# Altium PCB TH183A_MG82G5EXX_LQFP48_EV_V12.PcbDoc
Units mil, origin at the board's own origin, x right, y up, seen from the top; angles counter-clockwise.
Board outline 3155 x 2110 mil, 2 copper layers (Top Layer, Bottom Layer); 49 components, 63 nets, 295 pads, 183 vias.
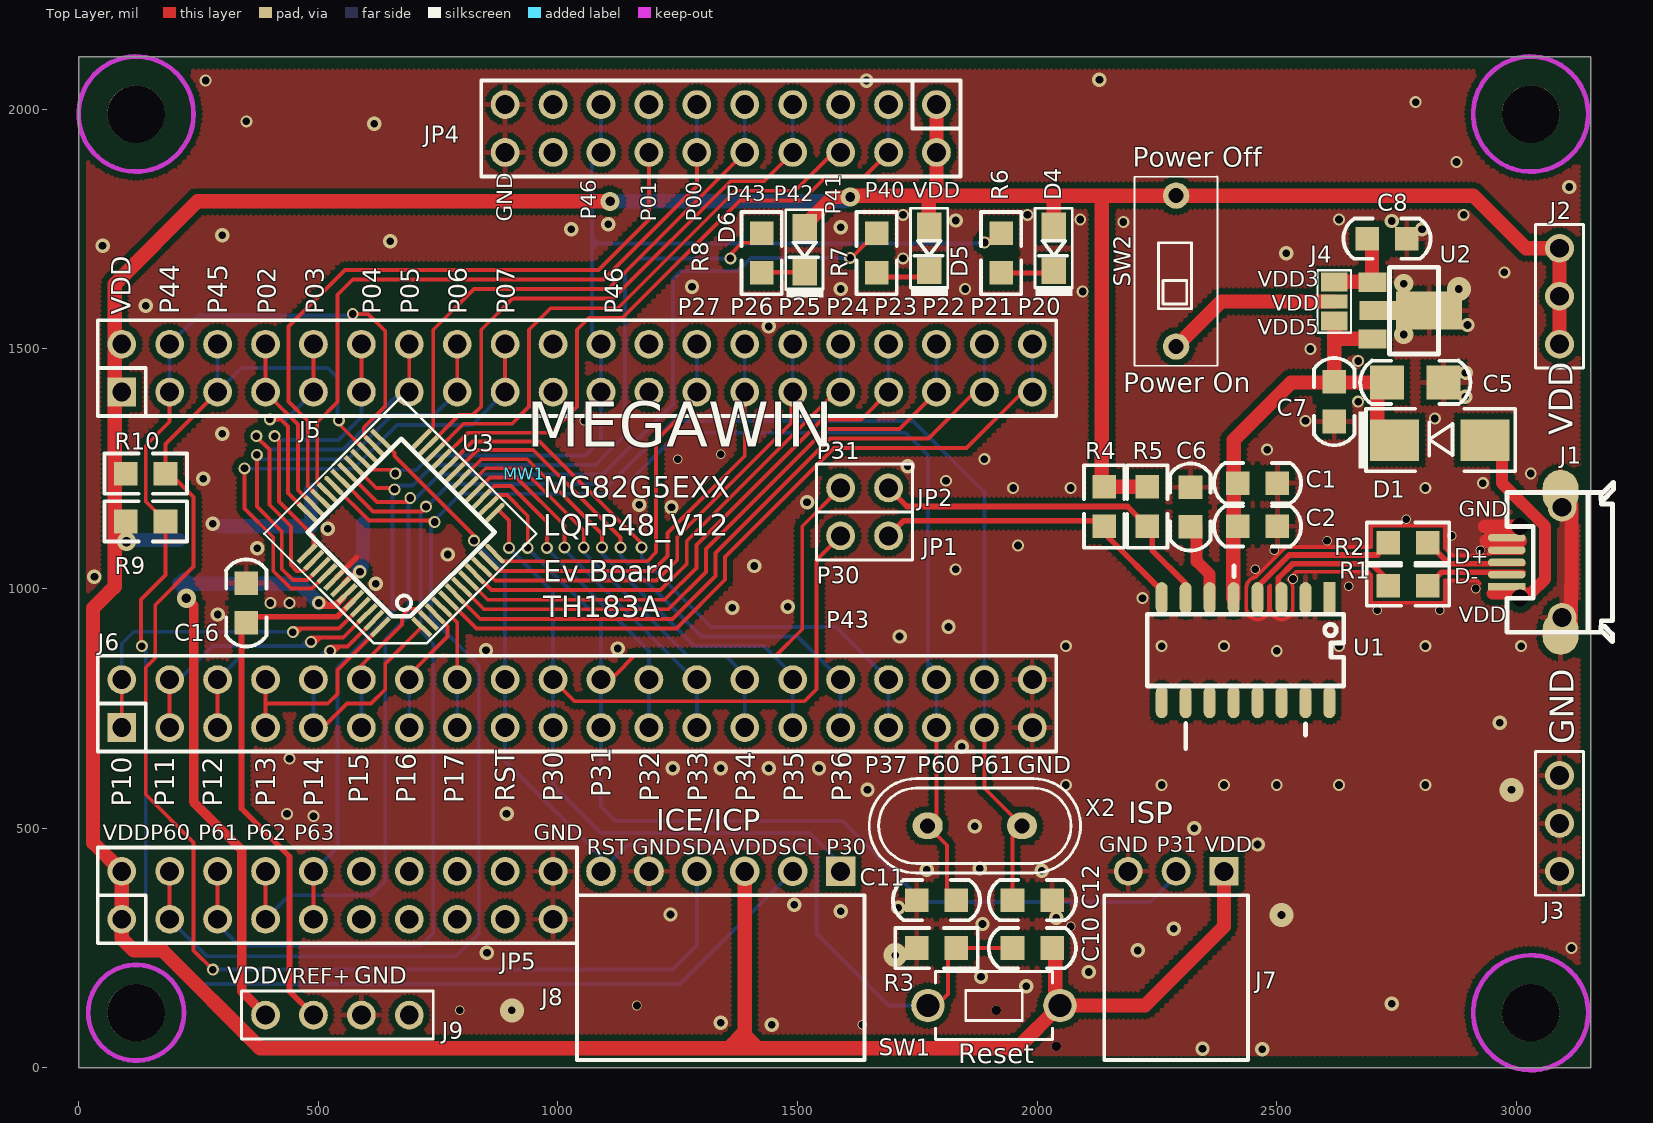
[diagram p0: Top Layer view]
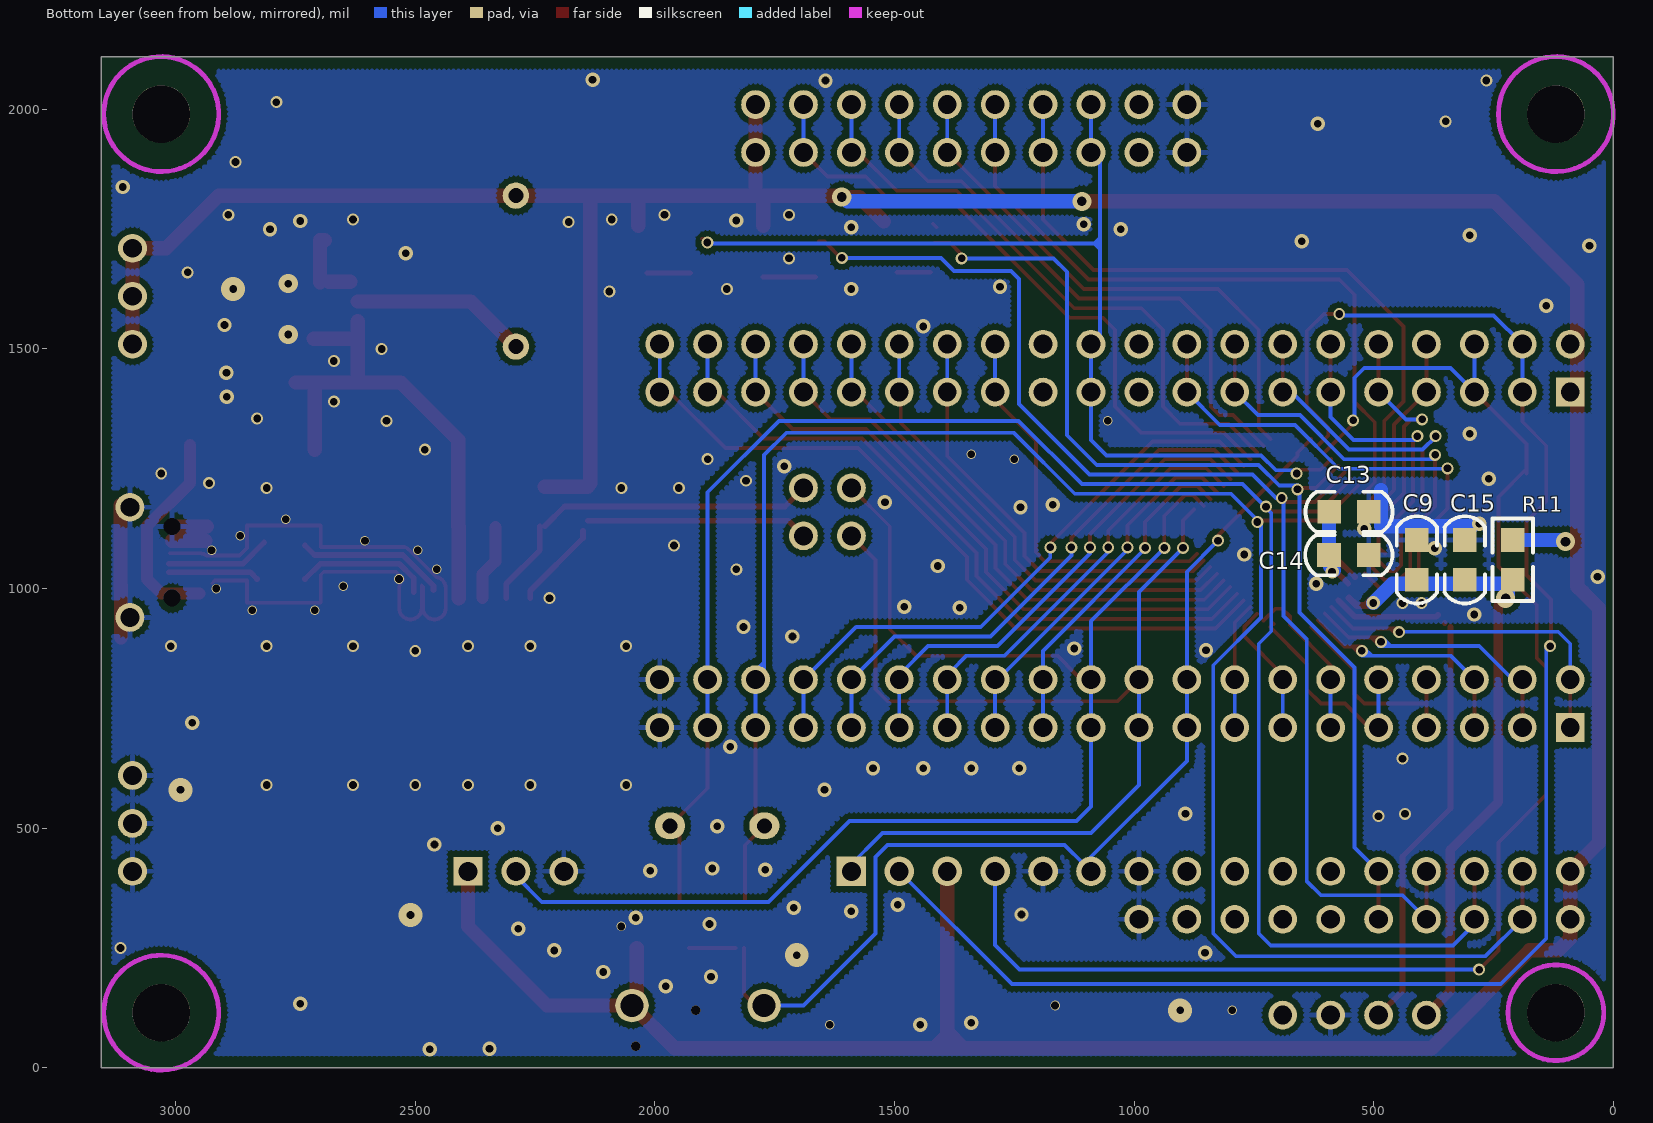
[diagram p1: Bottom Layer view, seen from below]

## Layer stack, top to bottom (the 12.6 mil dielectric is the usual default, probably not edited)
Top Layer: signal copper 1.4
Dielectric: dielectric 12.6, FR-4, Dk 4.8
Bottom Layer: signal copper 1.4

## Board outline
0,0 0,2110 3155,2110 3155,0

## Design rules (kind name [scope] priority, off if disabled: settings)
Clearance 12 [All] p1 off: gap=12
Clearance 7 [All] p2 off: gap=7
Clearance 6 [All] p3: gap=6
ComponentClearance [All] p1 off: gap=10 collisioncheckmode=3 verticalgap=10 showdistances=FALSE
HoleSize [All] p1: absolutevalues=TRUE maxlimit=500 minlimit=1 maxpercent=80.000 minpercent=20.000
MinimumSolderMaskSliver [All] p1 off: minsoldermaskwidth=10
PolygonConnect VIA [ISVIA] p1: connectstyle=Direct reliefconductorwidth=10 reliefentries=4 polygonreliefangle="90 Angle"
PolygonConnect [All] p2: connectstyle=Relief reliefconductorwidth=10 reliefentries=4 polygonreliefangle="90 Angle"
RoutingVias [All] p1: holewidth=16 width=25 viastyle="Through Hole" minholewidth=16 minwidth=24 maxholewidth=28 maxwidth=50
SilkToSilkClearance [All] p1 off: silktosilkclearance=10
SilkscreenOverComponentPads [All] p1 off: minsilkscreentomaskgap=10
SolderMaskExpansion [All] p1 off: expansion=4
Width [All] p1: maxlimit=200 minlimit=6 preferedwidth=10
23 further rules are at their usual default settings.

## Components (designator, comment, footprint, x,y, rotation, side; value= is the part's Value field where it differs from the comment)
C1 "4.7uF" 0805C 2460,1220 r0 top
C2 "0.1uF" 0805C 2460,1130 r0 top
C5 "4.7uF" 1206C 2789.06,1430 r0 top
C6 "1uF" 0805C 2320,1170 r90 top
C7 "0.1uF" 0805C 2620,1390 r270 top
C8 "4.7uF" 0805C 2730,1730 r0 top
C9 "0.1uF" 0805C 410,1060 r90 bottom
C10 "1u" 0805C 1990,250 r180 top
C11 "NC" 0805C 1790,350 r180 top
C12 "NC" 0805C 1990,350 r0 top
C13 "4.7uF" 0805C 551.61,1160 r180 bottom
C14 "0.1uF" 0805C 552,1070 r0 bottom
C15 "4.7uF" 0805C 310,1060 r90 bottom
C16 "0.1uF" 0805C 350,970 r90 top
D1 "1N5817" D5817_SMD_1 2840,1310 r0 top
D4 "Green" 0805D 2035,1710 r270 top
D5 "Red" 0805D 1775,1710 r270 top
D6 "Green" 0805D 1515,1706.92 r270 top
J1 "Micro USB母座" JACK_USB_SMD290X220P065 2980,1054.72 r180 top
J2 "*" PS3P254 3090,1510 r90 top
J3 "*" PS3P254 3090,610 r270 top
J4 "*" JUMP3_SMD 2620,1599 r90 top
J5 "CON40A" PS20X2P254 90,1410 r0 top locked
J6 "CON40A" PS20X2P254 90,710 r0 top locked
J7 "*" PS3P254f_90 2390,410 r180 top
J8 "*" PS6P254F_90 1590,410 r180 top locked
J9 "CON4" PS4P254 390,110 r0 top
JP1 "JUMPER2" PS2P254 1590,1110 r0 top
JP2 "JUMPER2" PS2P254 1590,1210 r0 top
JP4 "*" PS10X2P254 1790,2010 r180 top
JP5 "*" PS10X2P254 90,310 r0 top
MW1 "MW-A4" MEGAWIN_T 930,1240 r0 top
R1 "22" 0805R 2774,1006 r180 top
R2 "22" 0805R 2774,1096 r180 top
R3 "47K" 0805R 1790,250 r0 top
R4 "4.7K" 0805R 2140,1171.34 r270 top
R5 "4.7K" 0805R 2230,1171.34 r270 top
R6 "1K" 0805R 1925,1700 r270 top
R7 "1K" 0805R 1665,1700 r270 top
R8 "1K" 0805R 1425,1700 r270 top
R9 "4.7K" 0805R 140,1140 r180 top
R10 "4.7K" 0805R 140,1240 r180 top
R11 "10" 0805R 210,1060 r270 bottom
SW1 "SW TACT-SPST" SW_T_2P 1910,130 r180 top locked
SW2 "-" DIP2_SW 2290,1505.04 r90 top
U1 "MA111AS16" SO16_150P127 2435,871.5 r270 top
U2 "AIC1734-33(SOT-89)" SOT89 2700,1580 r270 top
U3 "MG82FG5EXX" LQFP48_7X7_050 672.94,1115.7 r45 top (schematic designator U1)
X2 "NC" X49U 1870,505 r180 top

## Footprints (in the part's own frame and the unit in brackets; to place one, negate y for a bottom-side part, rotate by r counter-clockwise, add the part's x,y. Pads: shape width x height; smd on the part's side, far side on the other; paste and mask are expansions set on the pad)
0805C [mm]
  rect 1.25x1.25 smd: 1(-1.05,0) 2(1.05,0)
  silkscreen extent -2.31,-1.07 2.31,1.07
0805D [mm]
  rect 1.4x1.3 smd: 1(-1.192,0) 2(1.192,0)
  silkscreen extent -2.12,-1 2.54,1
0805R [mm]
  rect 1.25x1.25 smd: 1(-1.05,0) 2(1.05,0)
  silkscreen extent -2.18,-1.07 2.18,1.07
1206C [mm]
  rect 1.8x1.8 smd: 1(-1.5,0) 2(1.5,0)
  silkscreen extent -2.92,-1.15 2.92,1.16
D5817_SMD_1 [mm]
  rect 2.6x2.2 smd: 1(2.39,0) 2(-2.39,0)
  silkscreen extent -4.3,-1.65 4,1.65
DIP2_SW [mm]
  round 1.4 hole 0.8: 1(0,0) 2(8,0)
  silkscreen extent -1.02,-2.2 9.02,2.2
JACK_USB_SMD290X220P065 [mm]
  rect 1.9x1.8 on Mech2: 0(-2.85,-1.15) 0(-2.85,1.15)
  round 0.8 hole 0.9 unplated: 1(-0.7,1.9) 5(-0.7,-1.9)
  rect 2x0.4 smd: 1(0,1.3)
  oval 2x0.4 smd: 2(0,0.65) 3(0,0) 4(0,-0.65) 5(0,-1.3)
  round 1.524 hole 1: 5(-2.931,2.921) 5(-2.931,-2.921)
  oval 1.9x2.3 smd: 5(-2.85,3.75) 5(-2.85,-3.75)
  silkscreen extent -5.65,-4.25 -0.01,4.2
JUMP3_SMD [mil]
  rect 40x55 smd: 1(-41,0) 3(41,0)
  rect 30x55 smd: 2(0,0)
  silkscreen extent -65,-35 65,35
LQFP48_7X7_050 [mm]
  rect 0.254x1.35 smd: 1(-2.75,-4.292) 2(-2.25,-4.292) 3(-1.75,-4.292) 4(-1.25,-4.292) 5(-0.75,-4.292) 6(-0.25,-4.292) 7(0.25,-4.292) 8(0.75,-4.292) 9(1.25,-4.292) 10(1.75,-4.292) 11(2.25,-4.292) 25(2.763,4.292) 26(2.263,4.292) 27(1.763,4.292) 28(1.263,4.292) 29(0.763,4.292) 30(0.263,4.292) 31(-0.237,4.292) 33(-1.237,4.292) 34(-1.737,4.292) 35(-2.237,4.292) 36(-2.737,4.292)
  oval 0.254x1.35 smd: 12(2.75,-4.292) 32(-0.737,4.292)
  oval 1.35x0.254 smd: 13(4.286,-2.744)
  rect 1.35x0.254 smd: 14(4.286,-2.244) 15(4.286,-1.744) 16(4.286,-1.244) 17(4.286,-0.744) 18(4.286,-0.244) 19(4.286,0.256) 20(4.286,0.756) 21(4.286,1.256) 22(4.286,1.756) 23(4.286,2.256) 24(4.286,2.756) 37(-4.286,2.756) 38(-4.286,2.256) 39(-4.286,1.756) 40(-4.286,1.256) 41(-4.286,0.756) 42(-4.286,0.256) 43(-4.286,-0.244) 44(-4.286,-0.744) 45(-4.286,-1.244) 46(-4.286,-1.744) 47(-4.286,-2.244) 48(-4.286,-2.744)
  silkscreen extent -5.15,-5.09 5.05,5.11
MEGAWIN_T [mil]
PS2P254 [mil]
  round 60 hole 39.37: 1(0,0) 2(100,0)
  silkscreen extent -50,-50 150,50
PS3P254 [mil]
  round 60 hole 39.37: 1(0,0) 2(100,0) 3(200,0)
  silkscreen extent -50,-50 250,50
PS3P254f_90 [mil]
  rect 60x60 hole 39.37: 1(0,0)
  round 60 hole 39.37: 2(100,0) 3(200,0)
  silkscreen extent -50,50 250,394
PS4P254 [mil]
  round 60 hole 39.37: 1(0,0) 2(100,0) 3(200,0) 4(300,0)
  silkscreen extent -50,-50 350,50
PS6P254F_90 [mil]
  rect 62x62 hole 39.37: 1(0,0)
  round 62 hole 39.37: 2(100,0) 3(200,0) 4(300,0) 5(400,0) 6(500,0)
  silkscreen extent -50,50 550,394
PS10X2P254 [mil]
  round 60 hole 39.37: 1(0,0) 2(0,100) 3(100,0) 4(100,100) 5(200,0) 6(200,100) 7(300,0) 8(300,100) 9(400,0) 10(400,100) 11(500,0) 12(500,100) 13(600,0) 14(600,100) 15(700,0) 16(700,100) 17(800,0) 18(800,100) 19(900,0) 20(900,100)
  silkscreen extent -50,-50 950,150
PS20X2P254 [mil]
  rect 60x60 hole 39.37: 1(0,0)
  round 60 hole 39.37: 2(0,100) 3(100,0) 4(100,100) 5(200,0) 6(200,100) 7(300,0) 8(300,100) 9(400,0) 10(400,100) 11(500,0) 12(500,100) 13(600,0) 14(600,100) 15(700,0) 16(700,100) 17(800,0) 18(800,100) 19(900,0) 20(900,100) 21(1000,0) 22(1000,100) 23(1100,0) 24(1100,100) 25(1200,0) 26(1200,100) 27(1300,0) 28(1300,100) 29(1400,0) 30(1400,100) 31(1500,0) 32(1500,100) 33(1600,0) 34(1600,100) 35(1700,0) 36(1700,100) 37(1800,0) 38(1800,100) 39(1900,0) 40(1900,100)
  silkscreen extent -50,-50 1950,150
SO16_150P127 [mil]
  rect 67x25 smd: 1(-108.5,175)
  oval 67x25 smd: 2(-108.5,125) 3(-108.5,75) 4(-108.5,25) 5(-108.5,-25) 6(-108.5,-75) 7(-108.5,-125) 8(-108.5,-175) 9(108.5,-175) 10(108.5,-125) 11(108.5,-75) 12(108.5,-25) 13(108.5,25) 14(108.5,75) 15(108.5,125) 16(108.5,175)
  silkscreen extent -176,-205 206,205
SOT89 [mm]
  rect 1.016x1.5 smd: 1(-1.5,0) 3(1.5,0)
  rect 2x3.5 smd: 2(0,3)
  rect 1.016x2.6 smd: 2(0,0.6)
  silkscreen extent -2.3,0.9 2.3,3.5
SW_T_2P [mil]
  round 70 hole 47.24: 1(-137.79,0) 2(137.79,0)
  silkscreen extent -122,-71 122,71
X49U [mm]
  oval 1.6x1.397 hole 0.8: 1(-2.5,0) 2(2.5,0)
  silkscreen extent -5.6,-2.5 5.6,2.5

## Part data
C1 C5 C8 C13 C15: library part CAP
C2 C6 C7 C9 C14 C16: library part "CAP NP"
C10: library part C
C11 C12: library part "C NP"
D1: library part DIODE_ZD, "Schottky Diode"
D4 D5 D6: library part LED
J1: library part CON5, "Connector"
J2 J3 J4 J7: library part CON3
J8: library part CON6
JP4 JP5: library part CON10X2
R1 R2 R3 R9 R10 R11: library part R
R4 R5 R6 R7 R8: library part R_Dup1
SW2: library part SW-2
U2: library part AIC1734-33(SOT-89)_0
U3: library part MG82FG5C64_LQFP48
X2: library part CRYSTAL

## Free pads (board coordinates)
  round 120 hole 120 unplated: 0(120,115) 0(120,1990) 0(3030,115) 0(3030,1990)

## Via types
v1: diameter 25, hole 16, Top Layer to Bottom Layer, tented both sides, 78 vias
v2: diameter 30, hole 16, Top Layer to Bottom Layer, tented both sides, 72 vias
v3: diameter 20, hole 16, Top Layer to Bottom Layer, tented both sides, 18 vias
v4: diameter 50, hole 16, Top Layer to Bottom Layer, tented both sides, 5 vias
v5: diameter 40, hole 20, Top Layer to Bottom Layer, tented both sides, 4 vias
v6: diameter 20, hole 20, Top Layer to Bottom Layer, tented both sides, 2 vias
v7: diameter 40, hole 16, Top Layer to Bottom Layer, tented both sides, 2 vias
v8: diameter 28, hole 16, Top Layer to Bottom Layer, tented both sides, 2 vias

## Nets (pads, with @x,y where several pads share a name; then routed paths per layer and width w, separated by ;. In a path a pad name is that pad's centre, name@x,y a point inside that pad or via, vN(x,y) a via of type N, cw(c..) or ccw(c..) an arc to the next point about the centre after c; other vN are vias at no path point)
CHIP_VDD: C9.1 C15.1 J9.1 R11.2 U3.43 | length 1345.2
  Top Layer w12: v8@509,976 518,967
  Top Layer w15: v8@510,965 535.8,965 U3.43@551.4,980.6
  Top Layer w20: v5(225,980) 240,965 240,555 340,455 340,160 J9.1
  Bottom Layer w30: R11.2@210,1010 R11.2@220,1010 ; v5@220,980 R11.2@220,1010 ; R11.2@220,1018.66 R11.2@220,1010 ; v8(501,970) 461,1010 R11.2@220,1010
D+: R2.2 U1.4 | length 311.8
  Top Layer w12: U1.4@2462,997 2462,1006 2526,1070 2710,1070 R2.2@2730,1090
D-: R1.2 U1.3 | length 281.1
  Top Layer w12: U1.3@2503.38,993.12 2503.38,1021.92 2533.46,1052 2698,1052 R1.2@2730,1020
GND_POWER: C1.2 C2.2 C5.2 C6.2 C7.2 C8.2 C9.2 C11.2 C12.2 C13.2 C14.1 C15.2 C16.2 J1.4 J1.5 J3.1 J3.2 J3.3 J6.39 J6.40 J7.3 J8.5 J9.3 JP4.19 JP4.20 JP5.19 JP5.20 R3.1 U1.2 U2.2 U3.41 | length 2332.8
  Top Layer w8: 2483.38,1003.34 2486.38,1006.33 2486.38,993.12 ; 2483.5,1001 2483.5,959 cw(c2460,959) 2436.5,959 2436.5,1001 cw(c2460,1001) 2456.14,1024.18 2513.96,1082 cw(c2526,1070) 2526,1087 ; 2486.5,991.07 2486.5,959 ccw(c2510,959) 2533.5,959 2533.5,1001 ccw(c2510,1001) 2524.77,1019.28 2540.5,1035 2690.96,1035 2697.05,1028.9 2697.05,970.39 2850.95,970.39 2850.95,1016.9 ; 2513.98,1082.02 cw(c2526,1070) 2526,1087 ; 2851.04,1017 2917.63,1017 2923.63,1011 ; J1.4@3011.5,1073.6 2948.5,1073.6 ccw(c2948.5,1054.72) 2936.16,1069 2866.38,1069 2850.95,1084.44 2850.95,1131.61 2697.05,1131.61 2697.05,1087 2526,1087
  Top Layer w12: U3.41@539.06,1023.94 580.16,1065.04
  Top Layer w30: 2934.48,1129.53 J1.5@3007.56,1129.53 ; 2938.2,1100 J1.5@3007.56,1100 ; J1.5@3114,898 3114,1005.8 ; 3115,1000 J1.5@3115,1174
  Bottom Layer w30: 295,1130 410,1130 413.39,1130 ; 414.34,1130 485,1130 485,1205.66
  other v1: 3115,250 490,525 435,530 2060,590 2260,590 2390,590 2500,590 2630,590 2810,590 440,645 2500,870 2060,880 2260,880 2390,880 2630,880 2810,880 3010,880 400,970 440,970 2220,980 1830,1040 1960,1090 1950,1210 2070,1210 2810,1210 2930,1220 1810,1225 3030,1240 1890,1270 2480,1290 2560,1350 2830,1355 2670,1390 2670,1475 2570,1500 2095,1620 1850,1625 2975,1660 1720,1689 2180,1765 2090,1770 2630,1770 1720,1780 1980,1780 2890,1780 2875,1890 350,1975 2790,2015 265,2060
  other v2: 2470,39 2345,40 1446,90 1340,94 2740,134 1977,170 1883,190 2108,200 852,240 2210,245 2285,290 1886,300 2040,313 1235,320 1590,327 1710,334 1493,340 2010,411 1770,413 1880,416 2460,466 2328,500 1870,504 893,530 1646,580 1240,625 1340,625 1440,625 1545,625 1843,670 2965,720 850,871 1125.15,874.85 1713,900 1815,920 290,946 1364,960 1480,962 620,1010 33,1025 1410,1047 770,1071 373,1084 520,1125 280,1135 1237,1170 1170,1175 1520,1180 260,1229 1730,1255 300,1323 2893,1400 2894,1450 1440,1547 2898,1550 140,1590 1590,1625 1280,1630 2520,1700 50,1715 650,1725 300,1737 1028,1750 2803,1750 1590,1754 1105,1760 2740,1767 1830,1768 3110,1838 617,1970 1644,2060 2130,2062
  other v3: 1635,90 795,120 1165,130 2070,295 2710,955 2840,955 2915,1000 2650,1005 2533.98,1020 2455,1040 2495,1080 2925,1080 2605,1100 2865,1110 2770,1145 1250,1270 1340,1280 1055,1350
  other v4: 904,120 1704,235 2510,319 2990,580 2880,1625
  other v6: 2040,45 1915,120
  other v7: 2765,1530 2765,1636.37
MA111_RX: JP2.2 R5.2 U1.7 | length 766.3
  Top Layer w12: JP2.2@1700,1220 JP2.2 1728.66,1171.34 2188.66,1171.34 R5.2 ; R5.2@2240,1130 2240,1080 2310,1010 U1.7
MA111_TX: JP1.2 R4.2 U1.8 | length 658.5
  Top Layer w12: JP1.2 1721.34,1141.34 R4.2@2140,1141.34 ; R4.2@2150,1120 2150,1105.34 2260,995.34 U1.8 U1.8@2260,990
NetC6_1: C6.1 U1.6 | length 159.8
  Top Layer w25: C6.1@2333,1128.66 2333,1057 2360,1030 U1.6
NetC13_1: C13.1 C14.2 U3.42 | length 139.7
  Top Layer w12: U3.42@552.98,1010.02 v8@582.97,1040
  Bottom Layer w30: v8@583.5,1038.5 591,1046 C14.2@591,1067 ; C14.2 C13.1@593.34,1135.66
  other v8: 587,1035
NetD1_1: D1.1 J1.1 | length 439.7
  Top Layer w25: 2950,990 3030,990 3060,1020 3060,1130 2970,1220 D1.1@2970,1300
NetD4_2: D4.2 R6.2 | length 91.7
  Top Layer w10: R6.2 D4.2@2016.74,1658.66
NetD5_2: D5.2 R7.2 | length 110
  Top Layer w10: R7.2@1665,1650 D5.2@1775,1650
NetD6_2: D6.2 R8.2 | length 70
  Top Layer w10: R8.2@1425,1660 D6.2@1495,1660
NetJ1_2: J1.2 R1.1 | length 189.8
  Top Layer w12: R1.1@2830,1020 2844,1034 J1.2@3014,1034
NetJ1_3: J1.3 R2.1 | length 216.9
  Top Layer w12: R2.1 2859.34,1052 J1.3@3014,1052
NetJ4_2: J4.2 SW2.1 | length 368.9
  Top Layer w30: SW2.1 2383.96,1599 J4.2
P00: JP4.11 JP4.12 U3.33 | length 1537.6
  Top Layer w8: 498,1307 498,1221.74 ; U3.33 498,1221.74 ; JP4.12 1290,1840 1095,1645 572,1645 540,1613 540,1389 498,1347 498,1221.74
  Bottom Layer w8: JP4.12 JP4.11
P01: JP4.13 JP4.14 U3.34 | length 1472.3
  Top Layer w8: U3.34 478,1213.9 478,1350 438,1390 438,1547 556,1665 1085,1665 1190,1770 JP4.14
  Bottom Layer w8: JP4.14 JP4.13
P02: J5.7 J5.8 U3.35 | length 401.6
  Top Layer w8: J5.8 390,1435 J5.7@416,1409 ; J5.7@400,1405 400,1400 458,1342 458,1206.07 U3.35
  Bottom Layer w8: J5.7@370,1410 J5.7
P03: J5.9 J5.10 U3.36 | length 495.5
  Top Layer w8: v1(399,1353) 422,1353 437,1338 437,1199.23 U3.36 ; J5.9@490,1386 J5.9 J5.10
  Bottom Layer w8: v1(399,1353) 433,1353 J5.9 J5.9@473,1410
P04: J5.11 J5.12 U3.37 | length 636.8
  Top Layer w8: v1(409,1318) 418,1309 418,1182 490,1110 490,1086.23 U3.37 ; J5.11 J5.12
  Bottom Layer w8: v1@409,1310 542,1310 590,1358 J5.11
P05: J5.13 J5.14 U3.38 | length 841.9
  Top Layer w8: v1@370.5,1317.5 398,1290 398,1175 443,1130 443,1049 456,1036 467.61,1036 U3.38 ; J5.13 J5.14
  Bottom Layer w8: v1@370.5,1317.5 398,1290 552,1290 672,1410 J5.13
  other v1: 371,1318
P06: J5.15 J5.16 U3.39 | length 947.1
  Top Layer w8: v1(372,1279) 372,1171 424,1119 424,1041 447,1018 477.45,1018 U3.39 ; J5.15 J5.16
  Bottom Layer w8: v1@372,1270 562,1270 653.87,1361.87 741.87,1361.87 J5.15 J5.15@780,1410
P07: J5.17 J5.18 U3.40 | length 1084.1
  Top Layer w8: v1@346,1250 346,1167 406,1107 406,1037 443,1000 487.29,1000 U3.40 ; J5.17@890,1427.01 J5.18
  Bottom Layer w8: v1@346,1250 573,1250 664.32,1341.32 821.32,1341.32 J5.17 ; J5.17@881.49,1418.51 J5.17@890,1427.01
  other v1: 346,1251
P10: J6.1 J6.2 U3.45 | length 721.6
  Top Layer w8: J6.1 J6.2 ; v1@447,917 465,917 ; v1@450,902 465,917 ; U3.45 543.48,917 465,917
  Bottom Layer w8: J6.2 90,885 115,910 v1@440,910 ; v1@440,909 v1@440,910 ; v1@443,913 v1@440,910
  other v1: 447,909
P11: J6.3 J6.4 U3.46 | length 618.4
  Top Layer w8: J6.3 J6.4@190,790 ; v1@485,898 500,898 ; v1@491,889 500,898 ; v1@492,885 505,898 ; U3.46 552.32,898 505,898 ; 500,898 505,898
  Bottom Layer w8: J6.4@190,790 280,880 465,880 ; v1@479.5,894.5 465,880 ; v1(485,889) 476,880 ; v1@489,880 476,880 ; 465,880 476,880
P12: J6.5 J6.6 U3.47 | length 523.3
  Top Layer w8: J6.5 J6.6 ; v1@525,878.99 545,878.99 ; v1@532,865.99 545,878.99 ; U3.47 561.15,878.99 545,878.99
  Bottom Layer w8: J6.6 340,860 505,860 ; v1@520,875 505,860 ; v1@525,860 515,860 ; v1(525,870) 515,860 ; 505,860 515,860
P13: J6.7 J6.8 U3.48 | length 435.6
  Top Layer w8: J6.7 390,760 ; J6.8 390,760 ; U3.48 540,830 540,780 520,760 390,760
P14: J6.9 J6.10 U3.1 | length 464.4
  Top Layer w8: J6.9 510,710 560,760 610,760 640,790 640,843.77 U3.1 ; J6.10@490,800 500,810 J6.10@515,810 ; U3.1@709.26,926.26 U3.1@710,927
  Bottom Layer w8: J6.9 J6.10@490,800
P15: J6.11 J6.12 U3.2 | length 338.7
  Top Layer w8: J6.12 590,840 675,925 675,942 691,958 705.36,958 U3.2
  Bottom Layer w8: J6.11 J6.12
P16: J6.13 J6.14 U3.3 | length 281.8
  Top Layer w8: J6.14@689.71,810 J6.14 690,820 770,900 770,921.2 U3.3
  Bottom Layer w8: J6.13 J6.14
P17: J6.15 J6.16 U3.4 | length 264.8
  Top Layer w8: U3.4 790,929.04 J6.16
  Bottom Layer w8: J6.15 J6.16
P20: J5.39 J5.40 U3.5 | length 1575
  Top Layer w8: U3.5 830.12,916.76 1247.46,916.76 1349,1018.29 1349,1066.01 1575.99,1293 1853,1293 1970,1410 J5.39
  Bottom Layer w8: J5.39 J5.40
P21: J5.37 J5.38 U3.6 | length 1450.2
  Top Layer w8: U3.6 837.96,936.76 1239.18,936.76 1329,1026.58 1329,1074.29 1567.71,1313 1773,1313 1870,1410 J5.37
  Bottom Layer w8: J5.37 J5.38
P22: J5.35 J5.36 U3.7 | length 1325.5
  Top Layer w8: U3.7 845.8,956.76 1230.89,956.76 1309,1034.86 1309,1082.58 1559.42,1333 1713,1333 J5.35
  Bottom Layer w8: J5.35 J5.36
P23: J5.33 J5.34 U3.8 | length 1200.8
  Top Layer w8: U3.8 853.64,976.76 1222.61,976.76 1289,1043.15 1289,1090.86 1551.14,1353 1633,1353 J5.33
  Bottom Layer w8: J5.33 J5.34
P24: J5.31 J5.32 U3.9 | length 1085.9
  Top Layer w8: U3.9 861.47,996.76 1214.32,996.76 1269,1051.43 1269,1099.15 J5.31@1579.85,1410 ; J5.31@1570,1410 J5.31@1579.85,1410 ; J5.31 J5.31@1579.85,1410
  Bottom Layer w8: J5.31 J5.32
P25: J5.29 J5.30 U3.10 | length 983.3
  Top Layer w8: U3.10 869.31,1016.76 1206.04,1016.76 1249,1059.72 1249,1107.43 1487.05,1345.48 J5.29@1487.05,1405.09 ; J5.29 J5.29@1490,1412.01
  Bottom Layer w8: J5.29 J5.30
P26: J5.27 J5.28 U3.11 | length 904.7
  Top Layer w8: U3.11 877.15,1036.76 1197.76,1036.76 1229,1068 1229,1115.72 1390,1276.72 J5.27
  Bottom Layer w8: J5.27 J5.28
P27: J5.25 J5.26 U3.12 | length 819.9
  Top Layer w8: U3.12 884.75,1057 1187,1057 1205,1076 1205,1309 1290,1394 J5.25
  Bottom Layer w8: J5.25 J5.26
P30/RXD: J6.19 J6.20 J8.1 JP1.1 U3.13 | length 2222.7
  Top Layer w8: U3.13@875,1165 898,1142 v1(898,1085) ; v1@899,1086 v1@900,1085 ; J6.20 1035,765 1515,765 1540,790 1540,1060 JP1.1
  Bottom Layer w8: v1(898,1085) 990,993 J6.20 J6.19 990,590 1090,490 1525,490 J8.1@1597.5,417.5
P31/TXD: J6.21 J6.22 J7.2 JP2.1 U3.14 | length 2876.2
  Top Layer w8: U3.14 877.16,1195 894,1195 937,1152 v1(937,1085) ; J6.22@1100,820 1120,820 ; J6.22@1110,810 1120,820 ; JP2.1 1510,1130 1510,915 1455,860 1160,860 1120,820
  Bottom Layer w8: v1(937,1085) 1090,932 J6.22 J6.21 1090,545 1120,515 1594,515 1763,346 2236,346 J7.2@2290,400
P32: J6.23 J6.24 U3.15 | length 695.7
  Top Layer w8: U3.15 868.13,1213.81 902.19,1213.81 977,1139 v1(977,1085)
  Bottom Layer w8: v1(977,1085) 977,1083 1190,870 J6.24 J6.23
P33: J6.25 J6.26 U3.16 | length 778
  Top Layer w8: U3.16 858.48,1232 914,1232 1014,1132 v1(1014,1086)
  Bottom Layer w8: v1(1014,1086) 1014,1081 1282.5,812.5 1282.5,802.5 1290,795 J6.25
P34: J6.27 J6.28 U3.17 | length 907.1
  Top Layer w8: U3.17 849.64,1251 924,1251 1054,1121 v1(1054,1086)
  Bottom Layer w8: v1(1054,1086) 1054,1076 1270,860 1350,860 1382.5,827.5 1382.5,802.5 1390,795 J6.27
P35: J6.29 J6.30 U3.18 | length 1028.7
  Top Layer w8: U3.18 840.8,1270 936,1270 1092,1114 v1(1092,1086)
  Bottom Layer w8: v1(1092,1086) 1092,1073 1285,880 1430,880 1490,820 J6.30 J6.29
P36: J6.31 J6.32 U3.19 | length 1144.8
  Top Layer w8: U3.19 831.97,1289 948.74,1289 1131,1106.74 v1(1131,1086)
  Bottom Layer w8: v1(1131,1086) 1131,1069 1300,900 1500,900 J6.32 J6.31
P37: J6.33 J6.34 U3.20 | length 1262.7
  Top Layer w8: U3.20 822.13,1307 962,1307 1175,1094 v1(1175,1086)
  Bottom Layer w8: v1(1175,1086) 1175,1065 1320,920 1580,920 J6.34 J6.33
P40: JP4.3 JP4.4 U3.21 | length 1391.5
  Top Layer w8: U3.21 812.29,1325 985,1325 1040,1380 1040,1540 1065,1565 1135,1565 1380,1810 1510,1810 1560,1860 1640,1860 JP4.4
  Bottom Layer w8: JP4.4 JP4.3
P41: JP4.5 JP4.6 U3.22 | length 1299.7
  Top Layer w8: U3.22 803.45,1344 904,1344 940,1380 940,1540 985,1585 1125,1585 1370,1830 1495,1830 1575,1910 JP4.6
  Bottom Layer w8: JP4.6 JP4.5
P42: JP4.7 JP4.8 U3.23 | length 1207.9
  Top Layer w8: U3.23 793.61,1362 822,1362 840,1380 840,1540 905,1605 1115,1605 1360,1850 1430,1850 JP4.8
  Bottom Layer w8: JP4.8 JP4.7
P43: JP4.9 JP4.10 U3.24 | length 1133.4
  Top Layer w8: U3.24 740,1336.23 740,1540 825,1625 1105,1625 JP4.10@1370,1890 ; JP4.10@1370,1910 JP4.10
  Bottom Layer w8: JP4.10 JP4.9
P44: J5.3 J5.4 J8.2 R9.1 U3.26 | length 3580.6
  Top Layer w8: v1(131.82,880) 130,880 130,977 181.34,1028.34 R9.1 140,1181.34 140,1298 190,1348 ; R9.1@177.68,1145 R9.1@181.34,1145 ; 190,1349 J5.3 J5.3@190,1411 ; v1(572,1573) 604,1573 640,1537 640,1381 595,1336 595,1319.62 U3.26
  Bottom Layer w8: v1(131.82,880) 140,880 140,270 235,175 1255,175 J8.2 J8.2@1490,430 ; J5.3 J5.4 250,1570 v1@572,1570 ; J8.2@1510,410 J8.2@1510,415
P45: J5.5 J5.6 J8.4 R10.1 U3.27 | length 3139.4
  Top Layer w8: R10.1 R10.1@181.34,1250 ; v1(280,205) 240,245 240,470 140,570 140,835 160,855 160,966 240,1046 240,1191.34 R10.1@181.34,1250 ; J5.5@295,1410 J5.5 181.34,1301.34 R10.1@181.34,1250 ; v1@545,1350 545,1341.78 U3.27
  Bottom Layer w8: v1(280,205) 1239,205 1290,256 J8.4 ; J5.6 J5.5 ; J5.5@295,1410 J5.5 ; v1@540,1348 540,1440 520,1460 340,1460 J5.5
  other v1: 543,1351
P46: J5.21 J5.22 JP4.15 JP4.16 R6.1 U3.28 | length 2088.9
  Top Layer w8: U3.28 610.94,1248 655,1248 v1@656,1247 ; v1@1893.39,1730 R6.1@1902.05,1730
  Bottom Layer w8: v1@667.07,1247 704,1247 734.93,1277.93 1057.93,1277.93 1090,1310 J5.21 J5.22 ; J5.22@1071,1505 1071,1708 ; JP4.16@1071,1905 1071,1732 ; JP4.16 JP4.15 ; v1(1890.39,1722) 1888.39,1720 1083,1720 ; 1071,1708 1071,1720 ; 1071,1708 1083,1720 ; 1071,1720 1071,1732 ; 1071,1720 1083,1720 ; 1071,1732 1083,1720
  other v1: 661,1240
P60: C11.1 J6.35 J6.36 JP5.3 JP5.4 U3.32 X2.2 | length 4146.9
  Top Layer w8: JP5.3 JP5.4 ; U3.32 605.58,1142 734,1142 v1@737,1145 ; J6.35 1790,523.42 X2.2 1812,464.58 C11.1@1812,349
  Bottom Layer w8: JP5.3 267,233 788,233 835,280 835,404 ; v1@737,1145 735,1143 735,940 835,840 835,404 ; v1@745.07,1145 798,1197.93 1123.93,1197.93 1251,1325 1726,1325 1772,1279 1772,846 ; 835,510.45 835,404 ; J6.36@1772,809 1772,846 ; J6.35 J6.36 ; J6.36@1790,828 1772,846
  other v1: 743,1139
P61: C12.1 J6.37 J6.38 JP5.5 JP5.6 U3.31 X2.1 | length 3899
  Top Layer w8: JP5.5 JP5.6 ; U3.31 614.42,1161 717,1161 v1@726,1170 ; J6.37 1890,583.42 X2.1 1948.66,485.24 C12.1
  Bottom Layer w8: JP5.5 290,300 335,255 715,255 740,280 740,885 714,911 714,1158 v1@726,1170 ; v1@725,1169 v1@726,1170 ; J6.37 J6.38 1890,1201 1741,1350 1241,1350 1108.93,1217.93 773.93,1217.93 v1@726,1170
  other v1: 725,1171
P62: JP5.7 JP5.8 R7.1 U3.30 | length 2715.5
  Top Layer w8: JP5.7 JP5.8 ; U3.30 622.26,1181 686,1181 v1@692,1187 ; v1@1610,1688 R7.1@1643,1721 ; R7.1@1650,1721 R7.1@1643,1721 ; R7.1@1658,1724 1646,1724 R7.1@1643,1721
  Bottom Layer w8: JP5.7 440,360 610,360 640,390 640,895 688,943 v1@688,1187 ; v1@684,1189 v1(692,1189) 704.07,1189 753,1237.93 1092.93,1237.93 1240,1385 1240,1646 1257,1663 1376,1663 1403,1690 v1(1610,1690)
P63: JP5.9 JP5.10 R8.1 U3.29 | length 2271.6
  Top Layer w8: JP5.9 JP5.10 ; U3.29 621.1,1210 v1@662,1210 ; v1@1360,1686 v1(1360,1689) 1360,1697 1384.54,1721.54 R8.1@1417,1721.54 ; R8.1@1412.5,1753.84 R8.1@1420,1761.34
  Bottom Layer w8: JP5.10 540,460 540,835 655,950 655,1205 v1@660,1210 ; v1@656.5,1209.5 v1@662,1215 ; v1@658,1215 v1@662,1215 ; v1(1360,1689) 1168,1689 1140,1661 1140,1320 1077.93,1257.93 740.26,1257.93 697.33,1215 v1@662,1215
  other v1: 659,1207
RST: C10.2 J6.17 J6.18 J8.6 R3.2 SW1.2 U3.25 | length 2245
  Top Layer w8: U3.25 659,1283.46 659,1277 825,1111 v1(825,1100) ; SW1.2 1790,130 1814,154 R3.2@1814,250 ; R3.2 C10.2@1928.66,250
  Bottom Layer w8: v1(825,1100) 890,1035 J6.18 J6.17 890,640 1105,425 1145,465 1515,465 1540,440 1540,280 1690,130 SW1.2
VDD: C10.1 D4.1 D5.1 D6.1 J2.1 J2.2 J2.3 J5.1 J5.2 J7.1 J8.3 JP4.1 JP4.2 JP5.1 JP5.2 R4.1 R5.1 R9.2 R10.2 R11.1 SW1.1 SW2.2 | length 9169.3
  Top Layer w8: 51,993 64,993
  Top Layer w30: JP5.1@93,310 JP5.1 ; 459,41 490,41 ; v5(1109,1808) 248,1808 75.09,1635.09 75.09,1510 75.09,1410 75.09,1240 75.09,1140 75.09,1098 75.09,1004.09 64,993 30,959 30,470 JP5.2 JP5.1 ; J8.3 1390,75 ; D6.1@1522.54,1766 1573.54,1817 v5(1610,1817) ; v5@1608.5,1818.5 1610,1820 1790,1820 ; D5.1@1774,1756.92 1774,1810 ; JP4.1 JP4.2 1790,1820 ; D4.1 2035,1810 ; SW1.1@2037.79,130 C10.1@2037.79,250 ; R4.1@2135,1220 2135,1820 ; R4.1 R5.1 ; J7.1 2390,295 2225,130 SW1.1 1958.79,41 1416.79,41 ; J2.1 J2.2 J2.3 3020,1710 2910,1820 SW2.2 2135,1820 ; JP5.1 90,270 115,245 175,245 379,41 490,41 ; 490,41 1356,41 ; 1356,41 1390,75 ; 1356,41 1390,41 ; 1390,41 1416.79,41 ; 1390,41 1390,67.79 ; 1390,67.79 1416.79,41 ; 1390,67.79 1390,75 ; 1790,1820 2135,1820
  Bottom Layer w30: v5@103.34,1101.34 R11.1 ; v5(1109,1808) v5@1598,1808
  other v5: 100,1098
VDD3: C8.1 J4.3 U2.1 | length 142.7
  Top Layer w30: J4.3@2635,1640 U2.1@2680,1640 ; C8.1@2688.66,1726.77 2698.66,1726.77 U2.1@2698.66,1639.06
VDD5: C1.1 C2.1 C5.1 C7.1 D1.2 J4.1 U1.5 U2.3 | length 1053.9
  Top Layer w30: U1.5@2409,980 C2.1@2409,1130 ; C2.1@2410,1130 2410,1310 2530,1430 C5.1 C5.1@2750,1430 ; C7.1 J4.1 ; 2630,1520.94 U2.3 U2.3@2711.89,1520.94 ; D1.2@2710,1290 C5.1@2710,1415.66
VREF+: C16.1 J9.2 U3.44 | length 1107
  Top Layer w12: 340,750 340,740 ; C16.1@340,920 340,740 ; C16.1@352,928 C16.1@352,928.66 ; C16.1@366,944.66 369.66,941 539.64,941 U3.44 ; J9.2 440,160 440,441 340,541 340,740
pads on no net: J1.0 J5.19 J5.20 J5.23 J5.24 J9.4 JP4.17 JP4.18 JP5.11 JP5.12 JP5.13 JP5.14 JP5.15 JP5.16 JP5.17 JP5.18 U1.1 U1.9 U1.10 U1.11 U1.12 U1.13 U1.14 U1.15 U1.16

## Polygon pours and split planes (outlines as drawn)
GND_POWER on Top Layer "Bottom Layer-No Net" (hatched 90Degree grid 10 track 10, remove dead copper, pour order 1001): 20,29 3130,29 3130,2080 20,2080
GND_POWER on Bottom Layer "Bottom Layer-No Net" (hatched 90Degree grid 10 track 10, remove dead copper, pour order 1001): 20,29 3130,29 3130,2080 20,2080

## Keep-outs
Keep-Out Layer:
  circle w10: c3030,115 r120
  circle w10: c120,1990 r120
  circle w10: c120,115 r100
  circle w10: c3030,1990 r120

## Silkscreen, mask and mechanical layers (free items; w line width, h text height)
Top Overlay:
  text "Power Off" at 2200,1880 h40
  text "P40" at 1640,1815 h33
  text "VDD" at 1740,1815 h33
  text "P43" at 1350,1808 h33
  text "P42" at 1450,1808 h33
  text "P41" at 1590,1780 h33 r90
  text "P46" at 1080,1770 h33 r90
  text "GND" at 905,1765 h33 r90
  text "P01" at 1205,1765 h33 r90
  text "P00" at 1300,1765 h33 r90
  text "VDD3" at 2460,1630 h33
  text "VDD" at 2490,1580 h33
  text "P44" at 210,1572 h40 r90
  text "P45" at 310,1572 h40 r90
  text "P02" at 411,1572 h38 r90
  text "P03" at 511,1572 h38 r90
  text "P04" at 630,1572 h38 r90
  text "P05" at 710,1572 h38 r90
  text "P06" at 810,1572 h38 r90
  text "P07" at 910,1572 h38 r90
  text "P46" at 1135,1572 h38 r90
  text "VDD" at 109,1571 h40 r90
  text "P27" at 1250,1570 h35
  text "P26" at 1360,1570 h35
  text "P25" at 1460,1570 h35
  text "P24" at 1560,1570 h35
  text "P23" at 1660,1570 h35
  text "P22" at 1760,1570 h35
  text "P21" at 1860,1570 h35
  text "P20" at 1960,1570 h35
  text "VDD5" at 2460,1530 h33
  text "Power On" at 2180,1410 h40
  text "VDD" at 3118,1320 h50 r90
  text "P31" at 1540,1270 h35
  text "MG82G5EXX" at 970,1190 h45
  text "GND" at 2880,1150 h33
  text "LQFP48_V12" at 970,1110 h45
  text "D+" at 2870,1052 h33
  text "Ev Board" at 969,1014 h45
  text "P30" at 1540,1010 h35
  text "D-" at 2870,1010 h33
  text "TH183A" at 970,940 h45
  text "VDD" at 2880,930 h33
  text "P43" at 1560,917 h35
  text "GND" at 3120,675 h50 r90
  text "P37" at 1640,615 h35
  text "P60" at 1750,615 h35
  text "P61" at 1860,615 h35.43
  text "GND" at 1960,615 h35.43
  text "P31" at 1110,565 h40 r90
  text "RST" at 910,555 h40 r90
  text "P30" at 1010,555 h40 r90
  text "P32" at 1212,555 h40 r90
  text "P33" at 1312,555 h40 r90
  text "P34" at 1412,555 h40 r90
  text "P35" at 1512,555 h40 r90
  text "P36" at 1612,555 h40 r90
  text "P15" at 603.95,551.95 h40 r90
  text "P16" at 703.95,551.95 h40 r90
  text "P17" at 803.95,551.95 h40 r90
  text "P10" at 110,545 h40 r90
  text "P11" at 200,545 h40 r90
  text "P12" at 300,545 h40 r90
  text "P13" at 410,545 h40 r90
  text "P14" at 510,545 h40 r90
  text "ISP" at 2190,510 h45
  text "ICE/ICP" at 1205,495 h45
  text "VDD" at 50,475 h33
  text "P60" at 150,475 h33
  text "P61" at 250,475 h33
  text "P62" at 350,475 h33
  text "P63" at 450,475 h33
  text "GND" at 950,475 h33
  text "GND" at 2130,450 h33
  text "P31" at 2250,450 h33
  text "VDD" at 2350,450 h33
  text "RST" at 1060,445 h33
  text "GND" at 1155,445 h33
  text "SDA" at 1260,445 h33
  text "VDD" at 1360,445 h33
  text "SCL" at 1460,445 h33
  text "P30" at 1560,445 h33
  text "VDD" at 310,175 h35
  text "VREF+" at 415,175 h33
  text "GND" at 575,175 h35
  text "Reset" at 1835,10 h40
Mechanical 1:
  the board outline again, w13
Mechanical 2:
  circle w10: c3030,115 r120
  circle w10: c120,1990 r120
  circle w10: c120,115 r100
  circle w10: c3030,1990 r120

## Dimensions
0,2110 to 0,0 on Top Overlay
0,0 to 3155,0 on Top Overlay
